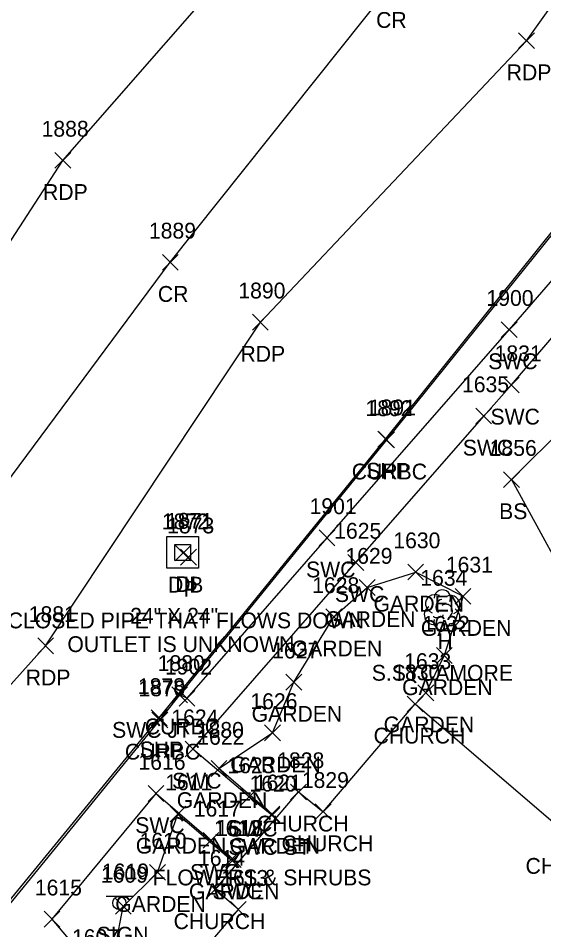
# Model space of a CAD drawing. Extents: x 1462668 to 1465147, y 550359 to 557351.
# Drawn here: x 1464725.3 to 1464791.7, y 552631.2 to 552746.4 of the extents above; entities that cross this region are included whole.
import ezdxf

# ---------------------------------------------------------------- set-up
doc = ezdxf.new("R2010")
doc.units = 0
for name, color, linetype in [('D_A', 7, 'Continuous'), ('D_C', 7, 'Continuous'), ('D_I', 7, 'Continuous'), ('D_TIC', 7, 'Continuous'), ('DS', 7, 'Continuous'), ('L_A', 7, 'Continuous'), ('L_C', 7, 'Continuous'), ('L_I', 7, 'Continuous'), ('L_TIC', 7, 'Continuous'), ('LAPB', 7, 'Continuous'), ('LBC', 7, 'Continuous'), ('LELB', 7, 'Continuous'), ('LTD', 7, 'Continuous'), ('P_A', 7, 'Continuous'), ('P_I', 7, 'Continuous'), ('P_TIC', 7, 'Continuous'), ('PET', 7, 'Continuous'), ('PRC', 7, 'Continuous'), ('PSP', 7, 'Continuous'), ('R_A', 7, 'Continuous'), ('R_I', 7, 'Continuous'), ('R_TIC', 7, 'Continuous'), ('RC', 7, 'Continuous'), ('RSW', 7, 'Continuous'), ('S_A', 7, 'Continuous'), ('S_I', 7, 'Continuous'), ('SSGN', 7, 'Continuous')]:
    doc.layers.add(name, color=color, linetype=linetype)

msp = doc.modelspace()

# ---------------------------------------------------------------- linework, layer by layer
at = {"layer": 'D_TIC'}
for points in [[(1464745.14, 552677.79), (1464747.14, 552679.79)], [(1464747.14, 552677.79), (1464745.14, 552679.79)], [(1464745.82, 552677.27), (1464747.82, 552679.27)], [(1464747.82, 552677.27), (1464745.82, 552679.27)]]:
    msp.add_lwpolyline(points, dxfattribs=at)
at = {"layer": 'DS'}
for p, q in [((1464744.09, 552680.86), (1464748.09, 552680.86)), ((1464744.09, 552676.86), (1464744.09, 552680.86)), ((1464748.09, 552680.86), (1464748.09, 552676.86)), ((1464745.09, 552677.86), (1464745.09, 552679.86)), ((1464745.09, 552679.86), (1464747.09, 552679.86)), ((1464747.09, 552679.86), (1464747.09, 552677.86)), ((1464746.09, 552678.86), (1464746.09, 552678.86)), ((1464746.09, 552678.86), (1464746.09, 552678.86)), ((1464747.09, 552677.86), (1464745.09, 552677.86)), ((1464748.09, 552676.86), (1464744.09, 552676.86))]:
    msp.add_line(p, q, dxfattribs=at)
at = {"layer": 'L_TIC'}
for points in [[(1464786.63, 552687.07), (1464788.63, 552689.07)], [(1464788.63, 552687.07), (1464786.63, 552689.07)], [(1464774.53, 552675.39), (1464776.53, 552677.39)], [(1464776.53, 552675.39), (1464774.53, 552677.39)], [(1464768.4, 552673.43), (1464770.4, 552675.43)], [(1464770.4, 552673.43), (1464768.4, 552675.43)], [(1464780.51, 552672.32), (1464782.51, 552674.32)], [(1464782.51, 552672.32), (1464780.51, 552674.32)], [(1464764.19, 552669.72), (1464766.19, 552671.72)], [(1464766.19, 552669.72), (1464764.19, 552671.72)], [(1464778.14, 552664.83), (1464780.14, 552666.83)], [(1464780.14, 552664.83), (1464778.14, 552666.83)], [(1464759.13, 552661.46), (1464761.13, 552663.46)], [(1464761.13, 552661.46), (1464759.13, 552663.46)], [(1464775.81, 552660.12), (1464777.81, 552662.12)], [(1464777.81, 552660.12), (1464775.81, 552662.12)], [(1464774.47, 552658.71), (1464776.47, 552660.71)], [(1464776.47, 552658.71), (1464774.47, 552660.71)], [(1464756.43, 552655.06), (1464758.43, 552657.06)], [(1464758.43, 552655.06), (1464756.43, 552657.06)], [(1464749.67, 552650.55), (1464751.67, 552652.55)], [(1464751.67, 552650.55), (1464749.67, 552652.55)], [(1464759.72, 552647.59), (1464761.72, 552649.59)], [(1464761.72, 552647.59), (1464759.72, 552649.59)], [(1464762.84, 552645.09), (1464764.84, 552647.09)], [(1464764.84, 552645.09), (1464762.84, 552647.09)], [(1464744.49, 552644.8), (1464746.49, 552646.8)], [(1464746.49, 552644.8), (1464744.49, 552646.8)], [(1464756.35, 552644.78), (1464758.35, 552646.78)], [(1464758.35, 552644.78), (1464756.35, 552646.78)], [(1464751.21, 552639.02), (1464753.21, 552641.02)], [(1464753.21, 552639.02), (1464751.21, 552641.02)], [(1464741.9, 552637.42), (1464743.9, 552639.42)], [(1464743.9, 552637.42), (1464741.9, 552639.42)], [(1464749.2, 552635.25), (1464751.2, 552637.25)], [(1464751.2, 552635.25), (1464749.2, 552637.25)], [(1464737.58, 552633.12), (1464739.58, 552635.12)], [(1464739.58, 552633.12), (1464737.58, 552635.12)], [(1464752.12, 552632.72), (1464754.12, 552634.72)], [(1464754.12, 552632.72), (1464752.12, 552634.72)]]:
    msp.add_lwpolyline(points, dxfattribs=at)
at = {"layer": 'LAPB'}
for points in [[(1464757.35, 552645.78), (1464750.67, 552651.55), (1464757.43, 552656.06), (1464760.13, 552662.46), (1464765.19, 552670.72), (1464769.4, 552674.43), (1464775.53, 552676.39), (1464781.51, 552673.32), (1464779.14, 552665.83), (1464776.81, 552661.12)], [(1464736.61, 552624), (1464738.58, 552634.12), (1464742.9, 552638.42), (1464745.49, 552645.8), (1464752.21, 552640.02)]]:
    msp.add_lwpolyline(points, dxfattribs=at)
at = {"layer": 'LBC'}
msp.add_lwpolyline([(1464741.39, 552619.99), (1464753.12, 552633.72), (1464750.2, 552636.25), (1464760.72, 552648.59), (1464763.84, 552646.09), (1464775.47, 552659.71), (1464794.67, 552643.24), (1464814.32, 552626.05)], dxfattribs=at)
at = {"layer": 'LELB'}
msp.add_lwpolyline([(1464879.78, 552700.74), (1464862.7, 552705.61), (1464836.07, 552712.41), (1464822.03, 552711.23), (1464810.25, 552718.32), (1464801.52, 552701.91), (1464787.63, 552688.07), (1464797.02, 552670.88)], dxfattribs=at)
at = {"layer": 'LTD'}
msp.add_line((1464778.85, 552671.65), (1464778.85, 552671.65), dxfattribs=at)
msp.add_line((1464778.85, 552671.65), (1464778.85, 552671.65), dxfattribs=at)
msp.add_arc((1464778.9, 552673.08), 1.05, 335.5272, 180.9563, dxfattribs=at)
for centre, major_axis, ratio, start_param, end_param in [((1464778.06, 552672.32), (1.21, -0.51), 0.895232, 1.570796, 4.712389), ((1464779.89, 552672.23), (-1.14, -0.48), 0.949671, 1.570796, 4.712389), ((1464778.64, 552672.11), (-0.208, -0.792), 0.645439, 3.141593, 6.283185), ((1464779.35, 552671.48), (-0.5, 0.667), 0.989748, 3.141593, 6.283185), ((1464777.77, 552670.94), (0.58, -1.04), 0.959034, 3.141593, 6.283185), ((1464779.85, 552670.82), (-1.09, 0.79), 0.841452, 1.570796, 4.712389), ((1464778.85, 552670.15), (0.26, 1.06), 0.942809, 1.570796, 4.712389), ((1464778.39, 552670.9), (-0.625, -0.083), 0.423636, 0, 3.141593)]:
    msp.add_ellipse(centre, major_axis=major_axis, ratio=ratio, start_param=start_param, end_param=end_param, dxfattribs=at)
at = {"layer": 'P_TIC'}
for points in [[(1464788.54, 552742.55), (1464790.54, 552744.55)], [(1464790.54, 552742.55), (1464788.54, 552744.55)], [(1464729.95, 552727.42), (1464731.95, 552729.42)], [(1464731.95, 552727.42), (1464729.95, 552729.42)], [(1464743.52, 552714.54), (1464745.52, 552716.54)], [(1464745.52, 552714.54), (1464743.52, 552716.54)], [(1464754.9, 552706.97), (1464756.9, 552708.97)], [(1464756.9, 552706.97), (1464754.9, 552708.97)], [(1464770.73, 552692.19), (1464772.73, 552694.19)], [(1464772.73, 552692.19), (1464770.73, 552694.19)], [(1464727.77, 552666.06), (1464729.77, 552668.06)], [(1464729.77, 552666.06), (1464727.77, 552668.06)], [(1464742.11, 552656.96), (1464744.11, 552658.96)], [(1464744.11, 552656.96), (1464742.11, 552658.96)]]:
    msp.add_lwpolyline(points, dxfattribs=at)
at = {"layer": 'PET'}
for points in [[(1464690.95, 552665.59), (1464705.97, 552689.95), (1464730.95, 552728.42), (1464756.78, 552757.93), (1464781.56, 552791.49), (1464804.1, 552812.88), (1464834.32, 552847.22), (1464855.04, 552863.89), (1464867.1, 552873.05), (1464879.3, 552886.59)], [(1464703.97, 552639.46), (1464728.77, 552667.06), (1464755.9, 552707.97), (1464789.54, 552743.55), (1464807.6, 552768.88), (1464825.2, 552787.71), (1464842.93, 552809.98), (1464865.69, 552832.75), (1464880.58, 552846.68), (1464904.1, 552869.16)]]:
    msp.add_lwpolyline(points, dxfattribs=at)
at = {"layer": 'PRC'}
msp.add_lwpolyline([(1464698.35, 552651.15), (1464716.32, 552677.6), (1464744.52, 552715.54), (1464772.1, 552750.17), (1464779.18, 552759.11), (1464796.25, 552779.04), (1464814.91, 552799.8), (1464849.7, 552834.84), (1464867.53, 552848.82), (1464892.14, 552871.14)], dxfattribs=at)
at = {"layer": 'PSP'}
msp.add_lwpolyline([(1464713.64, 552621.47), (1464720.3, 552630.09), (1464743.11, 552657.96), (1464771.73, 552693.19), (1464802.94, 552732.09), (1464806.7, 552736.72), (1464807.51, 552737.69), (1464827.96, 552762.61), (1464840.31, 552778.01), (1464860.3, 552803.04), (1464847.06, 552806.2), (1464846.96, 552807.41), (1464865.09, 552816), (1464884.93, 552820.04), (1464894.44, 552821.2), (1464905.2, 552819.49), (1464914.43, 552816.32), (1464923.05, 552811.38)], dxfattribs=at)
at = {"layer": 'R_TIC'}
for points in [[(1464786.33, 552706.03), (1464788.33, 552708.03)], [(1464788.33, 552706.03), (1464786.33, 552708.03)], [(1464786.62, 552699.03), (1464788.62, 552701.03)], [(1464788.62, 552699.03), (1464786.62, 552701.03)], [(1464783.12, 552695.11), (1464785.12, 552697.11)], [(1464785.12, 552695.11), (1464783.12, 552697.11)], [(1464770.87, 552692.09), (1464772.87, 552694.09)], [(1464772.87, 552692.09), (1464770.87, 552694.09)], [(1464763.32, 552679.71), (1464765.32, 552681.71)], [(1464765.32, 552679.71), (1464763.32, 552681.71)], [(1464766.97, 552676.6), (1464768.97, 552678.6)], [(1464768.97, 552676.6), (1464766.97, 552678.6)], [(1464744.71, 552659.87), (1464746.71, 552661.87)], [(1464746.71, 552659.87), (1464744.71, 552661.87)], [(1464745.63, 552659.43), (1464747.63, 552661.43)], [(1464747.63, 552659.43), (1464745.63, 552661.43)], [(1464742.2, 552656.68), (1464744.2, 552658.68)], [(1464744.2, 552656.68), (1464742.2, 552658.68)], [(1464746.39, 552653.01), (1464748.39, 552655.01)], [(1464748.39, 552653.01), (1464746.39, 552655.01)], [(1464741.72, 552647.39), (1464743.72, 552649.39)], [(1464743.72, 552647.39), (1464741.72, 552649.39)], [(1464753.47, 552646.95), (1464755.47, 552648.95)], [(1464755.47, 552646.95), (1464753.47, 552648.95)], [(1464756.36, 552644.64), (1464758.36, 552646.64)], [(1464758.36, 552644.64), (1464756.36, 552646.64)], [(1464748.66, 552641.47), (1464750.66, 552643.47)], [(1464750.66, 552641.47), (1464748.66, 552643.47)], [(1464751.49, 552639.03), (1464753.49, 552641.03)], [(1464753.49, 552639.03), (1464751.49, 552641.03)], [(1464728.58, 552631.5), (1464730.58, 552633.5)], [(1464730.58, 552631.5), (1464728.58, 552633.5)]]:
    msp.add_lwpolyline(points, dxfattribs=at)
at = {"layer": 'RC'}
msp.add_lwpolyline([(1464714.1, 552621.11), (1464713.72, 552621.38), (1464720.51, 552629.87), (1464743.2, 552657.68), (1464745.71, 552660.87), (1464771.87, 552693.09), (1464801.88, 552730.35), (1464803.14, 552731.98), (1464806.82, 552736.57), (1464807.62, 552737.53), (1464827.98, 552762.36), (1464840.55, 552777.99), (1464860.73, 552803.16), (1464848.01, 552806.27), (1464847.4, 552807.43), (1464865.21, 552815.86), (1464884.88, 552819.62), (1464894.44, 552820.83), (1464904.96, 552819.1), (1464914.17, 552815.93), (1464922.75, 552811.24)], dxfattribs=at)
at = {"layer": 'RSW'}
for points in [[(1464803.7, 552731.77), (1464804.73, 552729.59), (1464804.56, 552727.28), (1464803.42, 552725.63), (1464787.33, 552707.03), (1464764.32, 552680.71), (1464746.63, 552660.43)], [(1464757.36, 552645.64), (1464754.47, 552647.95), (1464747.39, 552654.01), (1464767.97, 552677.6), (1464784.12, 552696.11), (1464787.62, 552700.03), (1464807.52, 552723.23), (1464811.99, 552728.74), (1464843.13, 552721.25), (1464884.11, 552711.76)], [(1464746.63, 552660.43), (1464745.71, 552660.87)], [(1464775.81, 552584.52), (1464771.58, 552588.06), (1464763.13, 552589.19), (1464750.92, 552598.41), (1464744.22, 552610.75), (1464738.38, 552620.43), (1464734.92, 552626.23), (1464729.58, 552632.5), (1464742.72, 552648.39), (1464749.66, 552642.47), (1464752.49, 552640.03)]]:
    msp.add_lwpolyline(points, dxfattribs=at)
at = {"layer": 'SSGN'}
for p, q in [((1464736.43, 552635.4), (1464739.77, 552635.4)), ((1464738.08, 552634.56), (1464738.08, 552634.56))]:
    msp.add_line(p, q, dxfattribs=at)
msp.add_circle((1464738.08, 552634.56), 0.833, dxfattribs=at)

# ---------------------------------------------------------------- texts
at = {"layer": 'D_A'}
for s, p in [('DIB', (1464744.24, 552673.79)), ('DI', (1464745.15, 552673.86)), ('P', (1464746.2, 552673.27))]:
    msp.add_text(s, height=2, dxfattribs=at).set_placement(p)
at = {"layer": 'D_C'}
for s, p in [('ENCLOSED PIPE THAT FLOWS DOWN', (1464720.26, 552669.27)), ('24" X 24"', (1464739.45, 552669.86)), ('OUTLET IS UNKNOWN', (1464731.52, 552666.27))]:
    msp.add_text(s, height=2, dxfattribs=at).set_placement(p)
at = {"layer": 'D_I'}
for s, p in [('1872', (1464743.45, 552681.79)), ('1871', (1464743.97, 552681.86)), ('1873', (1464744.13, 552681.27))]:
    msp.add_text(s, height=2, dxfattribs=at).set_placement(p)
at = {"layer": 'L_A'}
for s, p in [('BS', (1464786.07, 552683.07)), ('GARDEN', (1464770.2, 552671.39)), ('GARDEN', (1464764.07, 552669.43)), ('GARDEN', (1464776.18, 552668.32)), ('H', (1464778.28, 552666.65)), ('GARDEN', (1464759.86, 552665.72)), ('GARDEN', (1464773.81, 552660.83)), ('GARDEN', (1464754.8, 552657.46)), ('GARDEN', (1464771.48, 552656.12)), ('CHURCH', (1464770.21, 552654.71)), ('GARDEN', (1464752.1, 552651.06)), ('GARDEN', (1464745.34, 552646.55)), ('CHURCH', (1464755.46, 552643.59)), ('GARDEN', (1464740.16, 552640.8)), ('GARDEN', (1464752.02, 552640.78)), ('CHURCH', (1464758.58, 552641.09)), ('CHURCH', (1464789.41, 552638.24)), ('GARDEN', (1464746.88, 552635.02)), ('GARDEN', (1464737.57, 552633.42)), ('CHURCH', (1464744.94, 552631.25))]:
    msp.add_text(s, height=2, dxfattribs=at).set_placement(p)
at = {"layer": 'L_C'}
for s, p in [('S.SYCAMORE', (1464769.98, 552662.65)), ('FLOWERS & SHRUBS', (1464742.3, 552636.78))]:
    msp.add_text(s, height=2, dxfattribs=at).set_placement(p)
at = {"layer": 'L_I'}
for s, p in [('1856', (1464784.88, 552691.07)), ('1630', (1464772.7, 552679.39)), ('1629', (1464766.65, 552677.43)), ('1631', (1464779.34, 552676.32)), ('1634', (1464776.11, 552674.65)), ('1628', (1464762.45, 552673.72)), ('1632', (1464776.4, 552668.83)), ('1627', (1464757.39, 552665.46)), ('1633', (1464774.07, 552664.12)), ('1830', (1464772.69, 552662.71)), ('1626', (1464754.64, 552659.06)), ('1622', (1464747.93, 552654.55)), ('1828', (1464758.03, 552651.59)), ('1611', (1464743.88, 552648.8)), ('1621', (1464755.18, 552648.78)), ('1829', (1464761.14, 552649.09)), ('1612', (1464750.03, 552643.02)), ('1610', (1464740.64, 552641.42)), ('1614', (1464748.02, 552639.25)), ('1609', (1464735.75, 552637.12)), ('1613', (1464750.95, 552636.72))]:
    msp.add_text(s, height=2, dxfattribs=at).set_placement(p)
at = {"layer": 'P_A'}
for s, p in [('CR', (1464770.53, 552745.17)), ('RDP', (1464787.03, 552738.55)), ('RDP', (1464728.44, 552723.42)), ('CR', (1464742.95, 552710.54)), ('RDP', (1464753.39, 552702.97)), ('SHP', (1464769.27, 552688.19)), ('RDP', (1464726.26, 552662.06)), ('SHP', (1464740.65, 552652.96))]:
    msp.add_text(s, height=2, dxfattribs=at).set_placement(p)
at = {"layer": 'P_I'}
for s, p in [('1888', (1464728.26, 552731.42)), ('1889', (1464741.82, 552718.54)), ('1890', (1464753.12, 552710.97)), ('1891', (1464769.61, 552696.19)), ('1881', (1464726.64, 552670.06)), ('1878', (1464740.42, 552660.96))]:
    msp.add_text(s, height=2, dxfattribs=at).set_placement(p)
at = {"layer": 'R_A'}
for s, p in [('SWC', (1464784.69, 552702.03)), ('SWC', (1464784.98, 552695.03)), ('SWC', (1464781.48, 552691.11)), ('CURBC', (1464767.45, 552688.09)), ('SWC', (1464761.68, 552675.71)), ('SWC', (1464765.33, 552672.6)), ('SWC JT 1880', (1464737.17, 552655.43)), ('CURBC', (1464741.3, 552655.87)), ('CURBC', (1464738.79, 552652.68)), ('SWC', (1464744.75, 552649.01)), ('SWC', (1464740.09, 552643.39)), ('SWC', (1464751.83, 552642.95)), ('SWC ST', (1464751.86, 552640.64)), ('SWC', (1464747.02, 552637.47)), ('SWC', (1464749.85, 552635.03))]:
    msp.add_text(s, height=2, dxfattribs=at).set_placement(p)
at = {"layer": 'R_I'}
for s, p in [('1900', (1464784.47, 552710.03)), ('1831', (1464785.5, 552703.03)), ('1635', (1464781.38, 552699.11)), ('1892', (1464769.18, 552696.09)), ('1901', (1464762.12, 552683.71)), ('1625', (1464765.23, 552680.6)), ('1880', (1464742.93, 552663.87)), ('1902', (1464743.85, 552663.43)), ('1879', (1464740.5, 552660.68)), ('1624', (1464744.65, 552657.01)), ('1616', (1464740.5, 552651.39)), ('1623', (1464751.73, 552650.95)), ('1620', (1464754.53, 552648.64)), ('1617', (1464747.49, 552645.47)), ('1618', (1464750.32, 552643.03)), ('1615', (1464727.41, 552635.5)), ('1607', (1464732.1, 552629.23))]:
    msp.add_text(s, height=2, dxfattribs=at).set_placement(p)
at = {"layer": 'S_A'}
msp.add_text('SIGN', height=2, dxfattribs=at).set_placement((1464735.22, 552629.54))
at = {"layer": 'S_I'}
msp.add_text('1619', height=2, dxfattribs=at).set_placement((1464735.88, 552637.54))

doc.saveas('drawing.dxf')
